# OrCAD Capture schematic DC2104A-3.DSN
size Custom; title: BOUNDARY MODE PFC CONTROLLER; rev: 3; note: DEMO CIRCUIT 2104A
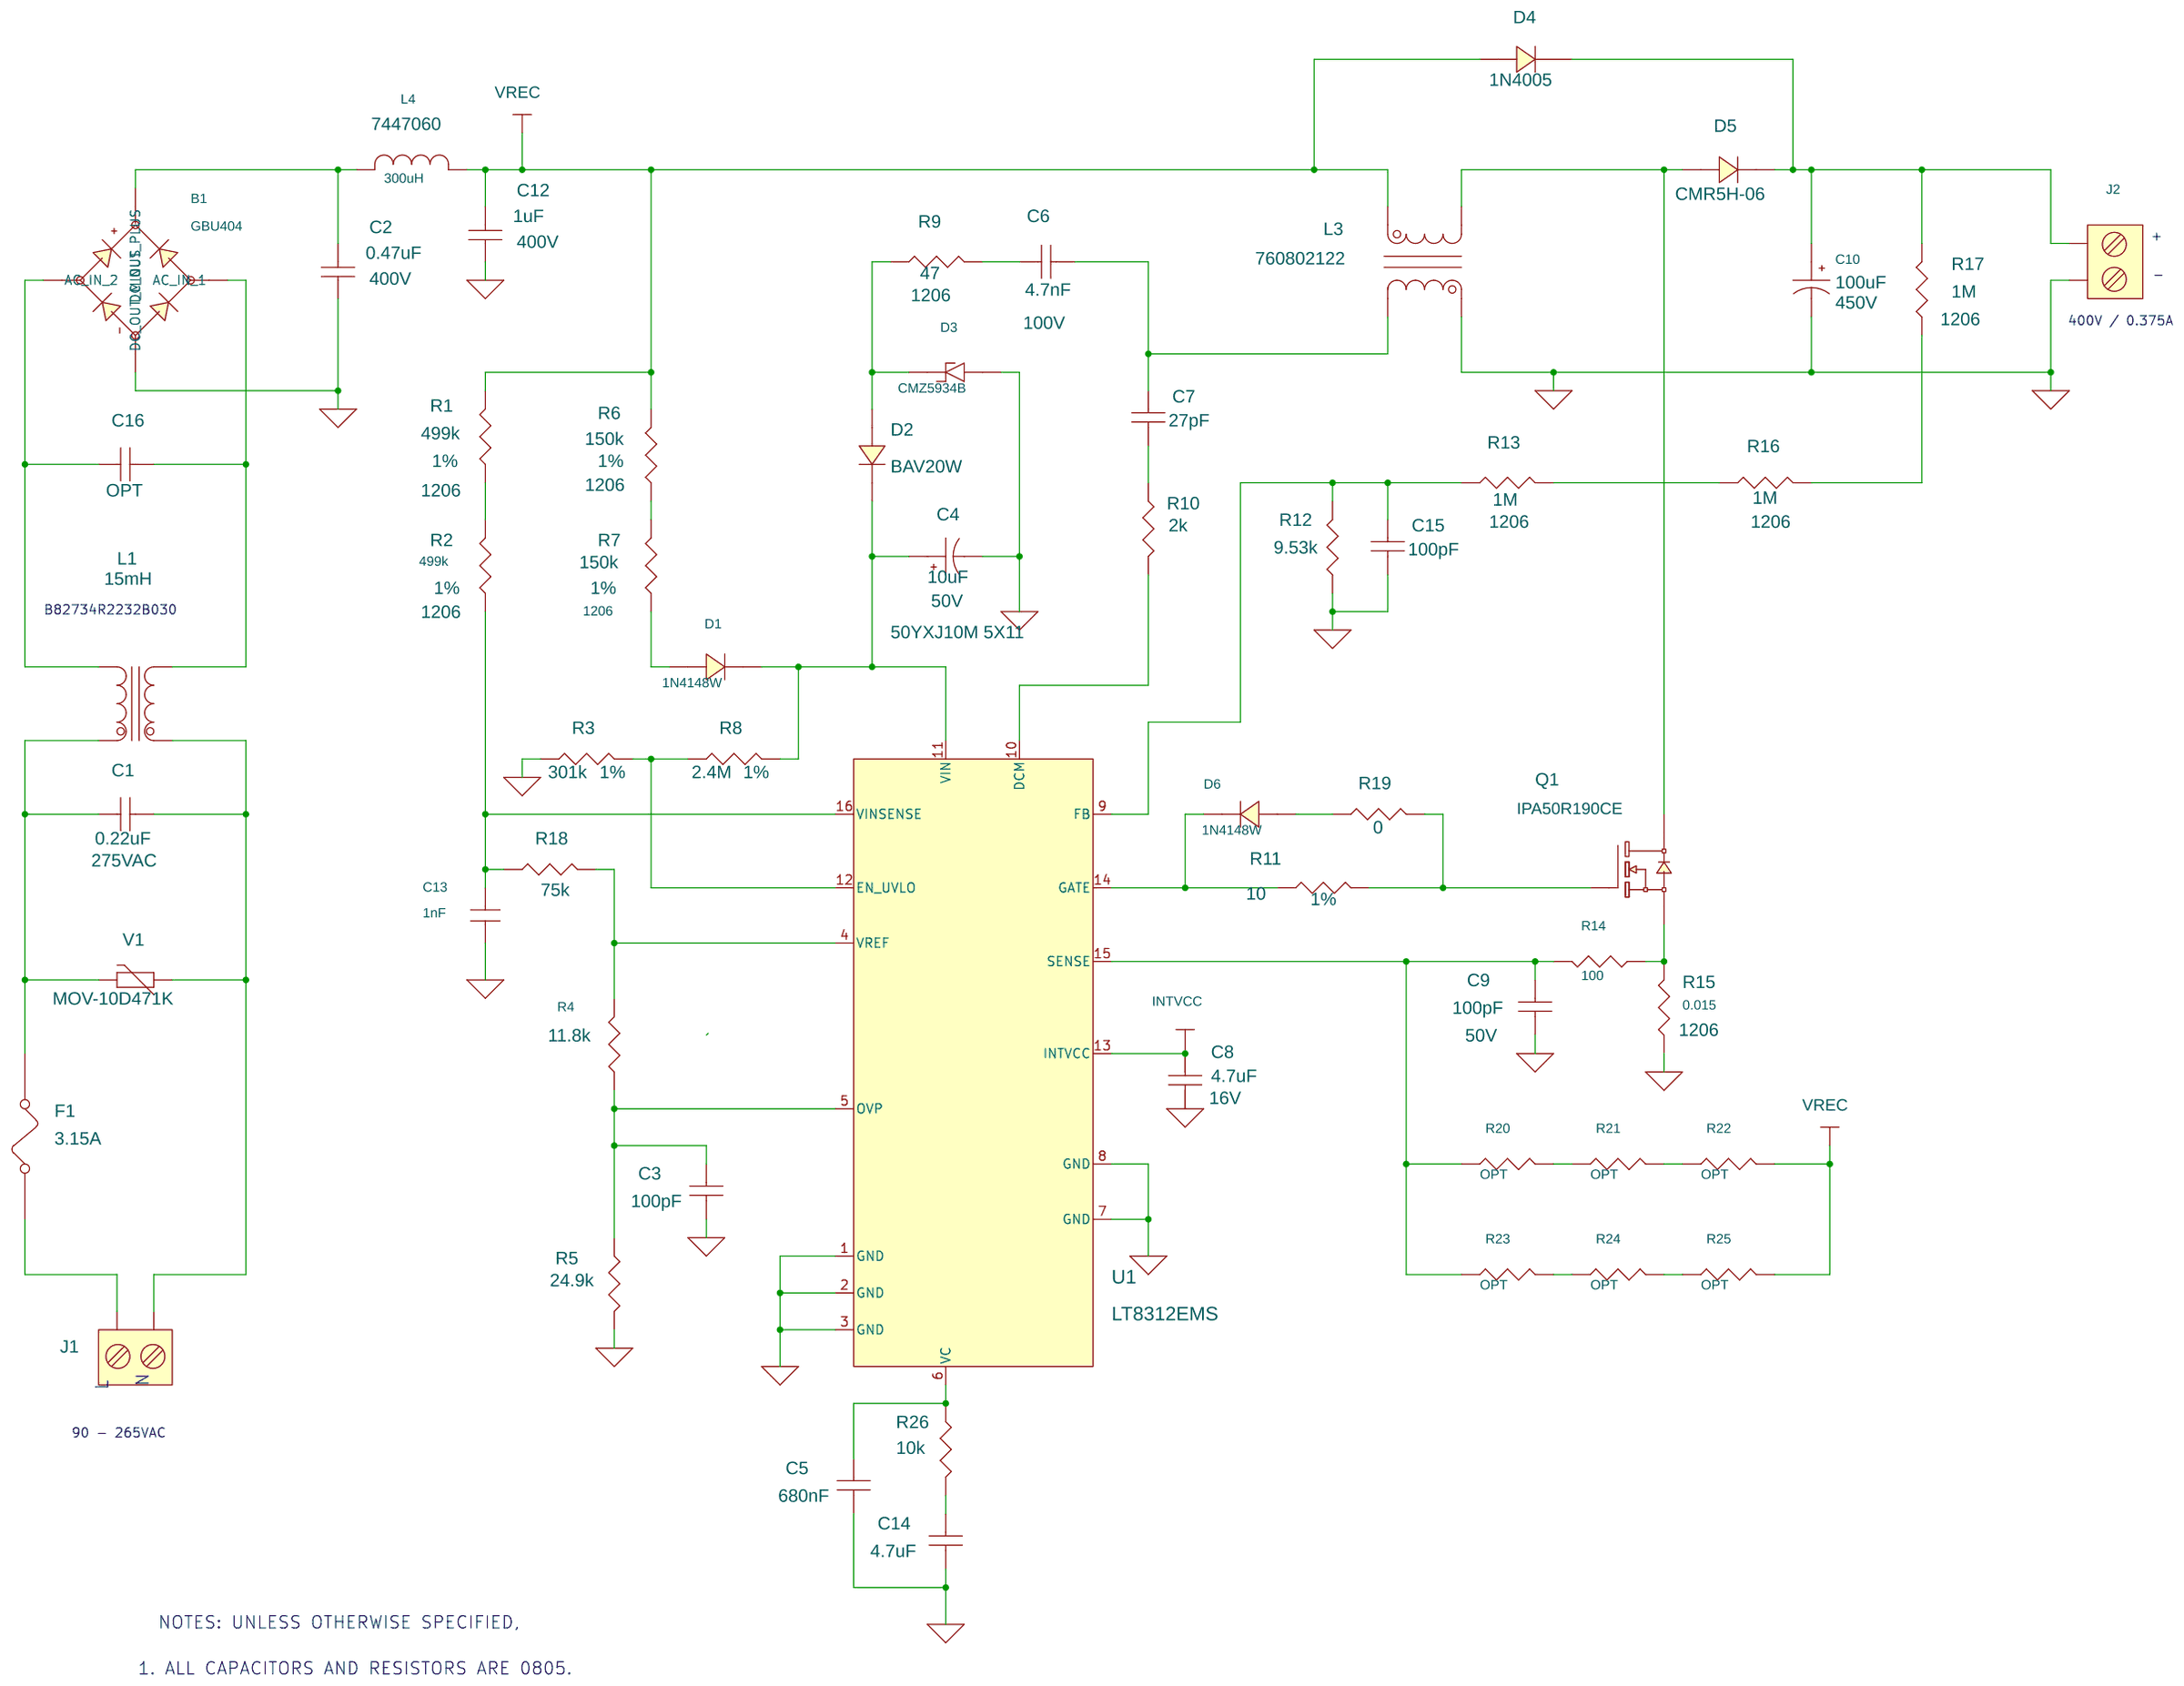
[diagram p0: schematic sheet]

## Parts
B1  GBU404  [GBU8A-GBU8M]
C1  0.22uF  [CAP-R46KI322000M2K]
C2  0.47uF  [CAP-ECWF4474]
C3  100pF  [0805]
C4  10uF  [CAP\RUBYCON\5X11]
C5  680nF  [0805]
C6  4.7nF  [0805]
C7  27pF  [0805]
C8  4.7uF  [0805]
C9  100pF  [0805]
C10  100uF  [CAP-VXH-22X25]
C12  1uF  [CAP-ECWF4105]
C13  1nF  [0805]
C14  4.7uF  [0805]
C15  100pF  [0805]
C16  OPT  [CAP-R46KI322000M2K]
D1  1N4148W  [SOD-123]
D2  BAV20W  [SOD123]
D3  CMZ5934B  [SMA]
D4  1N4005  [DO41-1N4001]
D5  CMR5H-06  [SMC]
D6  1N4148W  [SOD-123]
F1  3.15A  [FS_BSSMN_SS-5F]
J1  2 POSITION  [CONN\WDMLLR\1715250000]
J2  TERMINAL BLOCK  [CONN\WDMLLR\1715250000]
L1  15mH  [IND-B82734R]
L3  FLYBACK  [TRAN-760802122]
L4  300uH  [IND-7447060]
Q1  COOL MOS POWER TRANSISTOR  [TO-220\UP]
R1  499k  [1206]
R2  499k  [1206]
R3  301k  [0805]
R4  11.8k  [0805]
R5  24.9k  [0805]
R6  150k  [1206]
R7  150k  [1206]
R8  2.4M  [0805]
R9  47  [1206]
R10  2k  [0805]
R11  10  [0805]
R12  9.53k  [0805]
R13  1M  [1206]
R14  100  [0805]
R15  0.015  [1206]
R16  1M  [1206]
R17  1M  [1206]
R18  75k  [0805]
R19  0  [0805]
R20  OPT  [1206]
R21  OPT  [1206]
R22  OPT  [1206]
R23  OPT  [1206]
R24  OPT  [1206]
R25  OPT  [1206]
R26  10k  [0805]
U1  LT8312EMS  [MS-16L]
V1  MOV-10D471K  [TVS-MOV10D471K]

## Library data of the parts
B1 = GBPC608_0
C1 C16 = CAP_NP: CAP, 0.47uF 20% 310V POLYPREPYLENE; 1st Part Field: 275VAC; 2nd Part Field: 10%; 4th Part Field: KEMIT; 5th Part Field: R46KI322000M2K; 7th Part Field: CAP.,; Part Number: VISHAY BFC33820474; Tol: 20%; Voltage: 310V
C2 = EMK107BJ224KA: CAP, 0.47uF 20% 450V FILM; 1st Part Field: 400V; 2nd Part Field: 20%; 3rd Part Field: FILM; 4th Part Field: PANASONIC; 5th Part Field: ECWF4474JL; 7th Part Field: CAP.,; Part Number: RUBYCON 450MMK474K; Tol: 20%; Voltage: 310V
C3 C5 C14 = EMK107BJ224KA: CAP, 0603 0.1uF 10% 50V X7R; 1st Part Field: 25V; Part Number: AVX 06035C104KAT2A; Voltage: 50V
C4 = CAP_POL_0: CAP, 10uF 20% 50V ALUM; 1ST PART FIELD: 50YXJ10M 5X11; Part Number: RUBYCON 50YXJ10M 5X11; Voltage: 50V
C6 = 04023A221KAT2A: CAP, 0603 4.7pF +/-0.1pF 50V NP0; 1st Part Field: 100V; 6th Part Field: OPT; Part Number: AVX 06035A4R7CAT2A; Voltage: 50V
C7 C15 = 04023A221KAT2A: CAP, 0603 4.7pF +/-0.1pF 50V NP0; 6th Part Field: OPT; Part Number: AVX 06035A4R7CAT2A; Voltage: 50V
C8 = C4532X5R1H475M: CAP, 0805 4.7uF 20% 16V X5R; Part Number: AVX 0805YD475MAT2A; Voltage: 16V
C9 = EMK107BJ224KA: CAP, 0603 TBD; 1st Part Field: 25V; Part Number: TBD; Voltage: 50V
C10 = CAP_POL_0: CAP, 1000uF 20% 35V ELEC; Part Number: NIPPON CHEMI-CON ELXV350ETD102MK30S; Voltage: 450V
C12 = EMK107BJ224KA: CAP, 0.47uF 20% 450V FILM; 1st Part Field: 400V; 2nd Part Field: 20%; 3rd Part Field: FILM; 4th Part Field: PANASONIC; 5th Part Field: ECWF4105JL; 7th Part Field: CAP.,; Part Number: RUBYCON 450MMK474K; Tol: 20%; Voltage: 310V
C13 = CAP0805
D1 D6 = 1N4148W
D2 = 1N4448W_0: DIODE, FAST SWITCHING; Part Number: DIODES INC. BAV20W-7-F
D3 = mmsz5231_0.bt1
D4 D5 = 1N4448W_0: DIODE, FAST SWITCHING; Part Number: CENTRAL SEMI CMR1U-06M TR13
F1 = FUSE: FUSE, 3.15A, FAST ACTING; 4th Part Field: BUSSMAN; 5th Part Field: SS-5H-3.15; 7th Part Field: FUSE, FAST ACTING; Part Number: BUSSMAN SS-5H-3.15
J1 = CONN_TRBLK_5_1: TERMINAL BLOCK, 2 POSITION; 4th Part Field: WEIDMULLER; 5th Part Field: 1715250000; 7th Part Field: TERMINAL BLOCK,; Part Number: WEIDMULLER 1715250000
J2 = CONN_TRBLK_5_1: TERMINAL BLOCK, 2 POSITION; Part Number: WEIDMULLER 1715250000
L1 = TRAN_HM31_2: IND, 10mH COMMON MODE CHOKE; 4th Part Field: Sumida; 5th Part Field: LF2628NP-103; 7th Part Field: Inductor,; P L: LF2628NP-103; Part Number: SUMIDA LF2628NP-103
L3 = TRANSFORMER_FLAT_COMPACT_8: XFMR, FLYBACK; 4th Part Field: WURTH ELECTONIK; 5th Part Field: 760802122; 7th Part Field: XFMR,; Part Number: WURTH ELECTONIK 750811351
L4 = IND-744031003: 5TH PART FIELD: 7447060
Q1 = 2N7002_0: XSTR,  COOL MOS POWER TRANSISTOR; 4th Part Field: INFINEON; 5th Part Field: IPA50R190CE; 7th Part Field: XSTR,; Part Number: INFINEON SPP17N80C3
R1 R2 = RES0402: RES, 1206 499k OHMS 1% 1/4W; Part Number: VISHAY CRCW1206499KFKEA; Tol: 1%
R3 = RES0402: RES, 0603 124k OHMS 1% 1/10W; Part Number: VISHAY CRCW0603124KFKEA; Tol: 1%
R4 = CR05-2002FM: Part Number: VISHAY CRCW0603100KFKEA; Tol: 1%
R5 R26 = RES0402: 2nd Part Field: 1%; 3RD PART FIELD: Chip; Part Number: OPTION; Tol: <Tol>
R6 R7 = RES0402: RES, 1206 100k OHMS 1% 1/4W; Part Number: VISHAY CRCW1206100KFKEA; Tol: 1%
R8 = RES0402: RES, 0603 910k OHMS 1% 1/10W; Part Number: VISHAY CRCW0603910KFKEA; Tol: 1%
R9 = RES0402: RES, 0603 20 OHMS 1% 1/10W; Part Number: VISHAY CRCW060320R0FKEA; Tol: 5%
R10 R12 R13 R16 R17 = CJ18-000M: RES, 0603 2k OHMS 1% 1/10W; Part Number: VISHAY CRCW06032K00FKEA; Tol: 5%
R11 R19 = CR05-2002FM: RES, 0603 20 OHMS 1% 1/10W; Part Number: VISHAY CRCW060320R0FKEA; Tol: 1%
R14 = RES0402: RES, 0603 10 OHMS 5% 1/10W; Part Number: VISHAY CRCW060310R0JNEA
R15 = RES0402: RES, 1206 0.05 OHM 1% 1/4W; Part Number: VENKEL LCR1206-R050GT; Tol: 1%
R18 = RES0402: RES, 0603 124k OHMS 1% 1/10W; Part Number: VISHAY CRCW0603124KFKEA; Tol: 5%
R20-R25 = AAC-1206
U1 = LT3475EFE_1: IC, DUAL TRAIC DMMABLE OFFLINELED DRIVER
V1 = VARISTOR: Part Number: VISHAY VDRS10P320BSE

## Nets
GND: B1.4(DC_OUT_MINUS) C2.1 C3.2 C4.2 C5.2 C8.2 C9.2 C10.2 C12.1 C13.2 C14.2 C15.2 D3.2(AN) J2.2 L3.6 R3.1 R5.2 R12.2 R15.1 U1.1(GND) U1.2(GND) U1.3(GND) U1.7(GND) U1.8(GND)
INTVCC: C8.1 U1.13(INTVCC)
VREC: C12.2 D4.2(A) L3.3 L4.2 R1.1 R6.1 R22.2 R25.2
N08644: C4.1 D1.1 D2.1(K) R8.2 U1.11(VIN)
N08652: R3.2 R8.1 U1.12(EN_UVLO)
N08660: R10.2 U1.10(DCM)
N08944: R4.2 R18.2 U1.4(VREF)
N08952: C3.1 R4.1 R5.1 U1.5(OVP)
N09024: C9.1 R14.1 R20.1 R23.1 U1.15(SENSE)
N09098: Q1.1(G) R11.2 R19.2
N09408: C10.1 D4.1(K) D5.1(K) J2.1 R17.2
N09474: C7.2 R10.1
N09508: C13.1 R2.2 R18.1 U1.16(VINSENSE)
N09550: D1.2 R7.2
N09704: R1.2 R2.1
N09732: R6.2 R7.1
N10106: Q1.3(S) R14.2 R15.2
N10906: D6.1 R11.1 U1.14(GATE)
N10910: C15.1 R12.1 R13.1 U1.9(FB)
N234943: F1.1 J1.1
N234951: C1.2 J1.2 L1.1 V1.1
N235071: C1.1 F1.2 L1.2 V1.2
N235193: B1.2(AC_IN) C16.1 L1.3
N235197: B1.3(AC_IN_1) C16.2 L1.4
N351662: C6.2 C7.1 L3.7
N351843: C6.1 R9.2
N352171: D2.2(A) D3.1(CAT) R9.1
N364090: D5.2(A) L3.12 Q1.2(D)
N369190: R16.2 R17.1
N369595: R13.2 R16.1
N394076: B1.1(DC_OUT_PLUS) C2.2 L4.1
N467187: C5.1 R26.1 U1.6(VC)
N509066: D6.2 R19.1
N512144: R20.2 R21.1
N512356: R21.2 R22.1
N514551: R23.2 R24.1
N514555: R24.2 R25.1
N518243: C14.1 R26.2

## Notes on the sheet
- +
- -
- 400V / 0.375A
- B82734R2232B030
- N
- L
- 90 - 265VAC
- NOTES: UNLESS OTHERWISE SPECIFIED,
- 1. ALL CAPACITORS AND RESISTORS ARE 0805.
